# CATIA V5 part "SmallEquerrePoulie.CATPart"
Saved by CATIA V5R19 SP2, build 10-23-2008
Part number: SmallEquerrePoulie
Bounding box of the stored display mesh (mm): x -10 to 10, y 0 to 60, z 0 to 80
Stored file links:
  D:\SCHOOL\FRANCE\BANC_POUTRE_EN_MOUSSE\SmallEquerrePoulie.CATPart
  C:\Program Files\Dassault Systemes\B19\intel_a\reffiles\standard\MetricThickPitch.txt
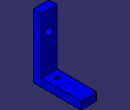
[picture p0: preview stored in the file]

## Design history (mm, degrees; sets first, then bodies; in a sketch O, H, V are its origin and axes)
AxisSystem1: origin (0, 0, 0), X (1, 0, 0), Y (0, 1, 0), Z (0, 0, 1)
Body1 (main body)
  Sketch1 on YZ plane of AxisSystem1, origin (0, 0, 0), H (0, 1, 0), V (0, 0, 1)
    point P1 (0, 80)
    line L1 (0, 80) -> (0, 0)
    line L2 (0, 0) -> (60, 0)
    line L3 (60, 0) -> (60, 10)
    line L4 (60, 10) -> (10, 10)
    line L5 (10, 10) -> (10, 80)
    line L6 (10, 80) -> (0, 80)
    length L6 = 10
    length L3 = 10
    length L2 = 60
    length L1 = 80
    coincidence: P1 V
    vertical: L1 V, L3 V, L5 V
    horizontal: L2 H, L4 H, L6 H
  Pad1: profile Sketch1, direction (1, 0, 0), length 10, opposite side length 10
  Sketch2 on face of Pad1 from Sketch1.L1, origin (-0.6083, 0, 43.0442), H (1, 0, 0), V (0, 0, 1)
    point P1 (0.6083, 12.9558)
    axis line L1 (0.6083, 27.4) -> (0.6083, -73.6539)
    reference intersected line E1 through (0.6083, 0) direction (0, 1) from YZ plane of AxisSystem1
    reference intersected line E2 through (0, -43.0442) direction (-1, 0) from XY plane of AxisSystem1
    distance E2 P1 = 56
    vertical: L1 V
    coincidence: L1 E1, L1 P1
  Hole1: placed by Sketch2, at (0, 0, 56) direction (0, 1, 0), diameter 10, through (limit type 6)
  Sketch3 on face of Pad1 from Sketch1.L2, origin (2.0625, 24.1251, 0), H (1, 0, 0), V (0, -1, 0)
    point P1 (-2.0625, 4.1251)
    axis line L1 (-2.0625, 45.5606) -> (-2.0625, -48.0425)
    reference intersected line E1 through (-2.0625, 0) direction (0, 1) from YZ plane of AxisSystem1
    reference intersected line E2 through (0, 24.1251) direction (1, 0) from ZX plane of AxisSystem1
    distance E2 P1 = 20
    vertical: L1 V
    coincidence: L1 E1, P1 L1
  Hole2: placed by Sketch3, at (0, 20, 0) direction (0, 0, 1), diameter 4.917, through (limit type 6)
